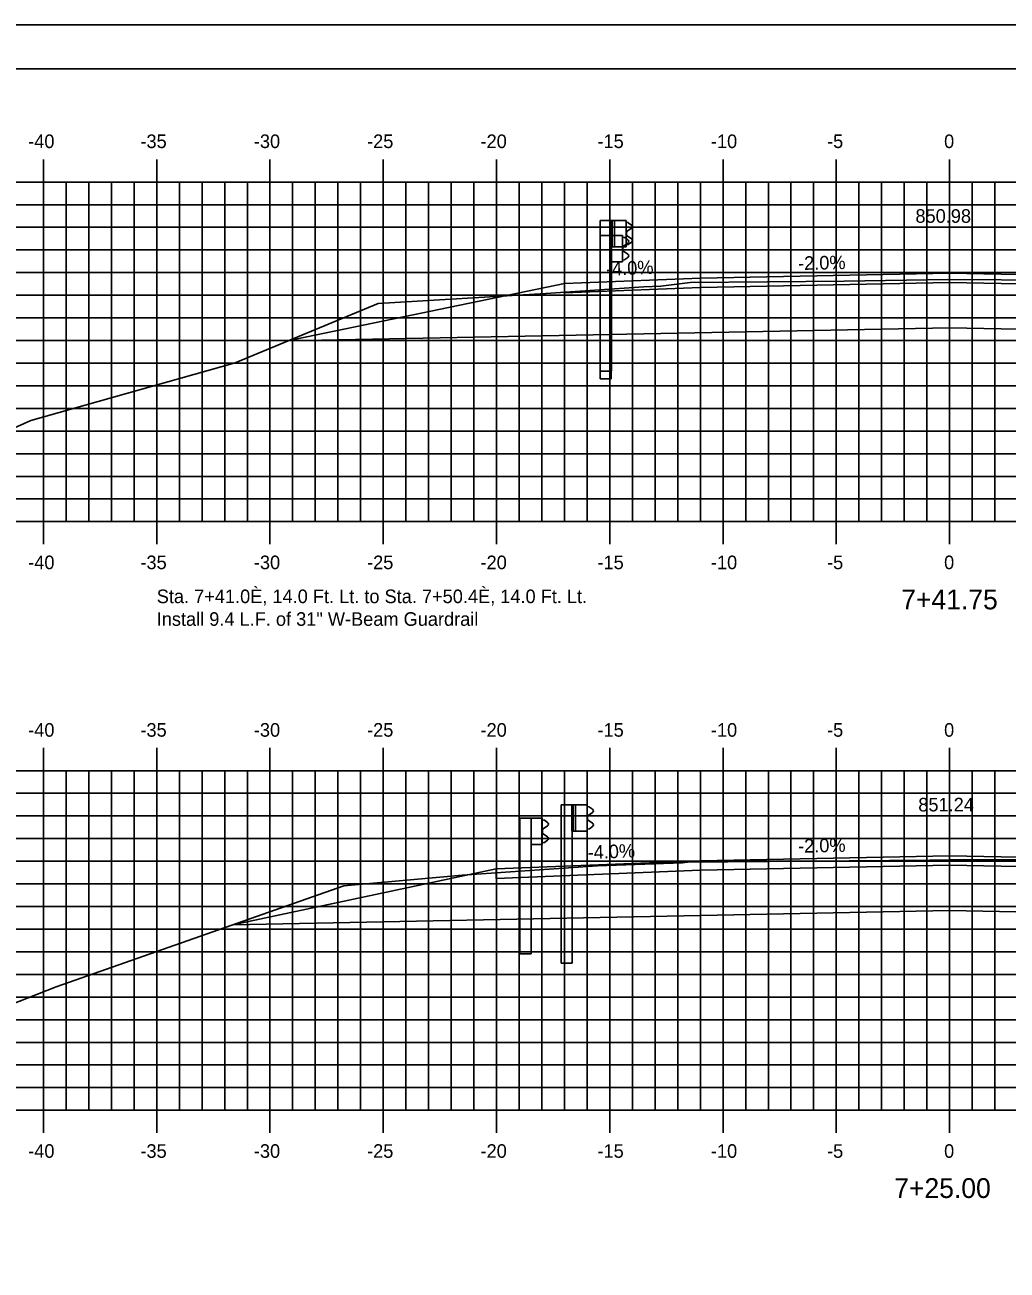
# Model space of a CAD drawing. Extents: x 2194004 to 2194525, y 863888 to 863998.
# Drawn here: x 2194214.2 to 2194257.5, y 863943.4 to 863998.4 of the extents above; entities that cross this region are included whole.
import ezdxf

# ---------------------------------------------------------------- set-up
doc = ezdxf.new("R2010")
doc.units = 0
for name, color, linetype in [('ANNOTATION', 7, 'Continuous'), ('BORDER', 7, 'Continuous'), ('D_Guardrail_Beam_Lt', 7, 'Continuous'), ('H_V ANNOTATION', 7, 'Continuous'), ('MAJOR', 7, 'Continuous'), ('MINOR', 7, 'Continuous'), ('PLOT BOUNDARY', 7, 'Continuous'), ('S_Guardrail_Beam', 7, 'Continuous'), ('S_Roadway_Centerline', 7, 'Continuous'), ('TEMPLATE', 7, 'Continuous')]:
    doc.layers.add(name, color=color, linetype=linetype)

msp = doc.modelspace()

# ---------------------------------------------------------------- linework, layer by layer
at = {"layer": 'BORDER'}
msp.add_lwpolyline([(2194179.986, 863891.446), (2194339.986, 863891.446), (2194339.986, 863996.446), (2194179.986, 863996.446)], close=True, dxfattribs=at)
at = {"layer": 'D_Guardrail_Beam_Lt'}
for p, q in [((2194239.557, 863989.752), (2194239.557, 863982.752)), ((2194240.028, 863989.752), (2194239.557, 863989.752)), ((2194240.715, 863989.752), (2194240.028, 863989.752)), ((2194240.028, 863989.752), (2194240.028, 863988.586)), ((2194240.09, 863989.752), (2194240.09, 863988.586)), ((2194240.195, 863989.752), (2194240.195, 863988.586)), ((2194240.715, 863988.586), (2194240.715, 863989.752)), ((2194240.715, 863989.669), (2194240.79, 863989.655)), ((2194240.805, 863989.648), (2194240.949, 863989.548)), ((2194240.72, 863989.204), (2194240.72, 863989.134)), ((2194240.949, 863989.405), (2194240.753, 863989.269)), ((2194240.753, 863989.07), (2194240.949, 863988.933)), ((2194240.028, 863988.586), (2194240.715, 863988.586)), ((2194240.049, 863982.752), (2194240.049, 863988.586)), ((2194240.79, 863988.684), (2194240.715, 863988.669)), ((2194240.949, 863988.79), (2194240.805, 863988.69)), ((2194240.049, 863982.752), (2194239.557, 863982.752)), ((2194237.836, 863963.944), (2194237.836, 863956.944)), ((2194238.307, 863963.944), (2194237.836, 863963.944)), ((2194238.994, 863963.944), (2194238.307, 863963.944)), ((2194238.307, 863963.944), (2194238.307, 863962.777)), ((2194238.369, 863963.944), (2194238.369, 863962.777)), ((2194238.474, 863963.944), (2194238.474, 863962.777)), ((2194238.994, 863962.777), (2194238.994, 863963.944)), ((2194238.994, 863963.86), (2194239.069, 863963.846)), ((2194239.084, 863963.839), (2194239.228, 863963.739)), ((2194238.999, 863963.395), (2194238.999, 863963.325)), ((2194239.228, 863963.596), (2194239.032, 863963.46)), ((2194239.032, 863963.261), (2194239.228, 863963.125)), ((2194238.307, 863962.777), (2194238.994, 863962.777)), ((2194238.328, 863956.944), (2194238.328, 863962.777)), ((2194239.069, 863962.875), (2194238.994, 863962.86)), ((2194239.228, 863962.982), (2194239.084, 863962.882)), ((2194238.328, 863956.944), (2194237.836, 863956.944))]:
    msp.add_line(p, q, dxfattribs=at)
for centre, major_axis, start_param, end_param in [((2194240.781, 863989.614), (0.0417, 0), 0.959931, 1.376053), ((2194240.898, 863989.476), (0.0877, 0), 5.323254, 7.243116), ((2194240.799, 863989.204), (-0.0789, 0), 5.323254, 6.283185), ((2194240.799, 863989.134), (-0.0789, 0), 6.283185, 7.243116), ((2194240.781, 863988.724), (0.0417, 0), 4.907132, 5.323254), ((2194240.898, 863988.862), (0.0877, 0), 5.323254, 7.243116), ((2194239.06, 863963.805), (0.0417, 0), 0.959931, 1.376053), ((2194239.177, 863963.667), (0.0877, 0), 5.323254, 7.243116), ((2194239.078, 863963.395), (-0.0789, 0), 5.323254, 6.283185), ((2194239.078, 863963.325), (-0.0789, 0), 6.283185, 7.243116), ((2194239.177, 863963.053), (0.0877, 0), 5.323254, 7.243116), ((2194239.06, 863962.916), (0.0417, 0), 4.907132, 5.323254)]:
    msp.add_ellipse(centre, major_axis=major_axis, ratio=0.995501, start_param=start_param, end_param=end_param, dxfattribs=at)
at = {"layer": 'MAJOR'}
for p, q in [((2194214.986, 863992.448), (2194214.986, 863991.446)), ((2194219.986, 863992.448), (2194219.986, 863991.446)), ((2194224.986, 863992.448), (2194224.986, 863991.446)), ((2194229.986, 863992.448), (2194229.986, 863991.446)), ((2194234.986, 863992.448), (2194234.986, 863991.446)), ((2194239.986, 863992.448), (2194239.986, 863991.446)), ((2194244.986, 863992.448), (2194244.986, 863991.446)), ((2194249.986, 863992.448), (2194249.986, 863991.446)), ((2194254.986, 863992.448), (2194254.986, 863991.446)), ((2194184.986, 863991.446), (2194324.986, 863991.446)), ((2194214.986, 863976.446), (2194214.986, 863991.446)), ((2194219.986, 863976.446), (2194219.986, 863991.446)), ((2194224.986, 863976.446), (2194224.986, 863991.446)), ((2194229.986, 863976.446), (2194229.986, 863991.446)), ((2194234.986, 863976.446), (2194234.986, 863991.446)), ((2194239.986, 863976.446), (2194239.986, 863991.446)), ((2194244.986, 863976.446), (2194244.986, 863991.446)), ((2194249.986, 863976.446), (2194249.986, 863991.446)), ((2194254.986, 863976.446), (2194254.986, 863991.446)), ((2194184.986, 863986.446), (2194324.986, 863986.446)), ((2194184.986, 863981.446), (2194324.986, 863981.446)), ((2194184.986, 863976.446), (2194324.986, 863976.446)), ((2194214.986, 863975.444), (2194214.986, 863976.446)), ((2194219.986, 863975.444), (2194219.986, 863976.446)), ((2194224.986, 863975.444), (2194224.986, 863976.446)), ((2194229.986, 863975.444), (2194229.986, 863976.446)), ((2194234.986, 863975.444), (2194234.986, 863976.446)), ((2194239.986, 863975.444), (2194239.986, 863976.446)), ((2194244.986, 863975.444), (2194244.986, 863976.446)), ((2194249.986, 863975.444), (2194249.986, 863976.446)), ((2194254.986, 863975.444), (2194254.986, 863976.446)), ((2194214.986, 863966.448), (2194214.986, 863965.446)), ((2194219.986, 863966.448), (2194219.986, 863965.446)), ((2194224.986, 863966.448), (2194224.986, 863965.446)), ((2194229.986, 863966.448), (2194229.986, 863965.446)), ((2194234.986, 863966.448), (2194234.986, 863965.446)), ((2194239.986, 863966.448), (2194239.986, 863965.446)), ((2194244.986, 863966.448), (2194244.986, 863965.446)), ((2194249.986, 863966.448), (2194249.986, 863965.446)), ((2194254.986, 863966.448), (2194254.986, 863965.446)), ((2194184.986, 863965.446), (2194324.986, 863965.446)), ((2194214.986, 863950.446), (2194214.986, 863965.446)), ((2194219.986, 863950.446), (2194219.986, 863965.446)), ((2194224.986, 863950.446), (2194224.986, 863965.446)), ((2194229.986, 863950.446), (2194229.986, 863965.446)), ((2194234.986, 863950.446), (2194234.986, 863965.446)), ((2194239.986, 863950.446), (2194239.986, 863965.446)), ((2194244.986, 863950.446), (2194244.986, 863965.446)), ((2194249.986, 863950.446), (2194249.986, 863965.446)), ((2194254.986, 863950.446), (2194254.986, 863965.446)), ((2194184.986, 863960.446), (2194324.986, 863960.446)), ((2194184.986, 863955.446), (2194324.986, 863955.446)), ((2194184.986, 863950.446), (2194324.986, 863950.446)), ((2194214.986, 863949.444), (2194214.986, 863950.446)), ((2194219.986, 863949.444), (2194219.986, 863950.446)), ((2194224.986, 863949.444), (2194224.986, 863950.446)), ((2194229.986, 863949.444), (2194229.986, 863950.446)), ((2194234.986, 863949.444), (2194234.986, 863950.446)), ((2194239.986, 863949.444), (2194239.986, 863950.446)), ((2194244.986, 863949.444), (2194244.986, 863950.446)), ((2194249.986, 863949.444), (2194249.986, 863950.446)), ((2194254.986, 863949.444), (2194254.986, 863950.446))]:
    msp.add_line(p, q, dxfattribs=at)
at = {"layer": 'MINOR'}
for p, q in [((2194215.986, 863976.446), (2194215.986, 863991.446)), ((2194216.986, 863976.446), (2194216.986, 863991.446)), ((2194217.986, 863976.446), (2194217.986, 863991.446)), ((2194218.986, 863976.446), (2194218.986, 863991.446)), ((2194220.986, 863976.446), (2194220.986, 863991.446)), ((2194221.986, 863976.446), (2194221.986, 863991.446)), ((2194222.986, 863976.446), (2194222.986, 863991.446)), ((2194223.986, 863976.446), (2194223.986, 863991.446)), ((2194225.986, 863976.446), (2194225.986, 863991.446)), ((2194226.986, 863976.446), (2194226.986, 863991.446)), ((2194227.986, 863976.446), (2194227.986, 863991.446)), ((2194228.986, 863976.446), (2194228.986, 863991.446)), ((2194230.986, 863976.446), (2194230.986, 863991.446)), ((2194231.986, 863976.446), (2194231.986, 863991.446)), ((2194232.986, 863976.446), (2194232.986, 863991.446)), ((2194233.986, 863976.446), (2194233.986, 863991.446)), ((2194235.986, 863976.446), (2194235.986, 863991.446)), ((2194236.986, 863976.446), (2194236.986, 863991.446)), ((2194237.986, 863976.446), (2194237.986, 863991.446)), ((2194238.986, 863976.446), (2194238.986, 863991.446)), ((2194240.986, 863976.446), (2194240.986, 863991.446)), ((2194241.986, 863976.446), (2194241.986, 863991.446)), ((2194242.986, 863976.446), (2194242.986, 863991.446)), ((2194243.986, 863976.446), (2194243.986, 863991.446)), ((2194245.986, 863976.446), (2194245.986, 863991.446)), ((2194246.986, 863976.446), (2194246.986, 863991.446)), ((2194247.986, 863976.446), (2194247.986, 863991.446)), ((2194248.986, 863976.446), (2194248.986, 863991.446)), ((2194250.986, 863976.446), (2194250.986, 863991.446)), ((2194251.986, 863976.446), (2194251.986, 863991.446)), ((2194252.986, 863976.446), (2194252.986, 863991.446)), ((2194253.986, 863976.446), (2194253.986, 863991.446)), ((2194255.986, 863976.446), (2194255.986, 863991.446)), ((2194256.986, 863976.446), (2194256.986, 863991.446)), ((2194184.986, 863990.446), (2194324.986, 863990.446)), ((2194184.986, 863989.446), (2194324.986, 863989.446)), ((2194184.986, 863988.446), (2194324.986, 863988.446)), ((2194184.986, 863987.446), (2194324.986, 863987.446)), ((2194184.986, 863985.446), (2194324.986, 863985.446)), ((2194184.986, 863984.446), (2194324.986, 863984.446)), ((2194184.986, 863983.446), (2194324.986, 863983.446)), ((2194184.986, 863982.446), (2194324.986, 863982.446)), ((2194184.986, 863980.446), (2194324.986, 863980.446)), ((2194184.986, 863979.446), (2194324.986, 863979.446)), ((2194184.986, 863978.446), (2194324.986, 863978.446)), ((2194184.986, 863977.446), (2194324.986, 863977.446)), ((2194215.986, 863950.446), (2194215.986, 863965.446)), ((2194216.986, 863950.446), (2194216.986, 863965.446)), ((2194217.986, 863950.446), (2194217.986, 863965.446)), ((2194218.986, 863950.446), (2194218.986, 863965.446)), ((2194220.986, 863950.446), (2194220.986, 863965.446)), ((2194221.986, 863950.446), (2194221.986, 863965.446)), ((2194222.986, 863950.446), (2194222.986, 863965.446)), ((2194223.986, 863950.446), (2194223.986, 863965.446)), ((2194225.986, 863950.446), (2194225.986, 863965.446)), ((2194226.986, 863950.446), (2194226.986, 863965.446)), ((2194227.986, 863950.446), (2194227.986, 863965.446)), ((2194228.986, 863950.446), (2194228.986, 863965.446)), ((2194230.986, 863950.446), (2194230.986, 863965.446)), ((2194231.986, 863950.446), (2194231.986, 863965.446)), ((2194232.986, 863950.446), (2194232.986, 863965.446)), ((2194233.986, 863950.446), (2194233.986, 863965.446)), ((2194235.986, 863950.446), (2194235.986, 863965.446)), ((2194236.986, 863950.446), (2194236.986, 863965.446)), ((2194237.986, 863950.446), (2194237.986, 863965.446)), ((2194238.986, 863950.446), (2194238.986, 863965.446)), ((2194240.986, 863950.446), (2194240.986, 863965.446)), ((2194241.986, 863950.446), (2194241.986, 863965.446)), ((2194242.986, 863950.446), (2194242.986, 863965.446)), ((2194243.986, 863950.446), (2194243.986, 863965.446)), ((2194245.986, 863950.446), (2194245.986, 863965.446)), ((2194246.986, 863950.446), (2194246.986, 863965.446)), ((2194247.986, 863950.446), (2194247.986, 863965.446)), ((2194248.986, 863950.446), (2194248.986, 863965.446)), ((2194250.986, 863950.446), (2194250.986, 863965.446)), ((2194251.986, 863950.446), (2194251.986, 863965.446)), ((2194252.986, 863950.446), (2194252.986, 863965.446)), ((2194253.986, 863950.446), (2194253.986, 863965.446)), ((2194255.986, 863950.446), (2194255.986, 863965.446)), ((2194256.986, 863950.446), (2194256.986, 863965.446)), ((2194184.986, 863964.446), (2194324.986, 863964.446)), ((2194184.986, 863963.446), (2194324.986, 863963.446)), ((2194184.986, 863962.446), (2194324.986, 863962.446)), ((2194184.986, 863961.446), (2194324.986, 863961.446)), ((2194184.986, 863959.446), (2194324.986, 863959.446)), ((2194184.986, 863958.446), (2194324.986, 863958.446)), ((2194184.986, 863957.446), (2194324.986, 863957.446)), ((2194184.986, 863956.446), (2194324.986, 863956.446)), ((2194184.986, 863954.446), (2194324.986, 863954.446)), ((2194184.986, 863953.446), (2194324.986, 863953.446)), ((2194184.986, 863952.446), (2194324.986, 863952.446)), ((2194184.986, 863951.446), (2194324.986, 863951.446))]:
    msp.add_line(p, q, dxfattribs=at)
at = {"layer": 'PLOT BOUNDARY'}
msp.add_lwpolyline([(2194171.893, 863888.387), (2194341.893, 863888.387), (2194341.893, 863998.387), (2194171.893, 863998.387)], close=True, dxfattribs=at)
at = {"layer": 'S_Guardrail_Beam'}
for p, q in [((2194239.565, 863989.091), (2194239.565, 863983.091)), ((2194240.057, 863989.091), (2194239.565, 863989.091)), ((2194240.546, 863989.091), (2194240.057, 863989.091)), ((2194240.057, 863989.091), (2194240.057, 863987.924)), ((2194240.546, 863987.924), (2194240.546, 863989.091)), ((2194240.546, 863989.018), (2194240.628, 863989.003)), ((2194240.645, 863988.996), (2194240.788, 863988.896)), ((2194240.559, 863988.553), (2194240.559, 863988.462)), ((2194240.788, 863988.753), (2194240.593, 863988.617)), ((2194240.057, 863983.091), (2194240.057, 863987.924)), ((2194240.057, 863987.924), (2194240.546, 863987.924)), ((2194240.628, 863988.011), (2194240.546, 863987.997)), ((2194240.593, 863988.397), (2194240.788, 863988.261)), ((2194240.788, 863988.118), (2194240.645, 863988.018)), ((2194240.057, 863983.091), (2194239.565, 863983.091)), ((2194236.018, 863963.352), (2194236.018, 863957.352)), ((2194236.51, 863963.352), (2194236.018, 863963.352)), ((2194236.999, 863963.352), (2194236.51, 863963.352)), ((2194236.51, 863963.352), (2194236.51, 863962.185)), ((2194236.999, 863962.185), (2194236.999, 863963.352)), ((2194236.999, 863963.279), (2194237.081, 863963.264)), ((2194237.098, 863963.257), (2194237.241, 863963.157)), ((2194237.012, 863962.814), (2194237.012, 863962.723)), ((2194237.241, 863963.014), (2194237.046, 863962.878)), ((2194237.046, 863962.658), (2194237.241, 863962.522)), ((2194236.51, 863957.352), (2194236.51, 863962.185)), ((2194236.51, 863962.185), (2194236.999, 863962.185)), ((2194237.081, 863962.272), (2194236.999, 863962.258)), ((2194237.241, 863962.379), (2194237.098, 863962.279)), ((2194236.51, 863957.352), (2194236.018, 863957.352))]:
    msp.add_line(p, q, dxfattribs=at)
for centre, major_axis, start_param, end_param in [((2194240.621, 863988.962), (0.0417, 0), 0.959931, 1.396263), ((2194240.638, 863988.553), (-0.0789, 0), 5.323254, 6.283185), ((2194240.638, 863988.462), (-0.0789, 0), 6.283185, 7.243116), ((2194240.738, 863988.825), (0.0877, 0), 5.323254, 7.243116), ((2194240.621, 863988.052), (0.0417, 0), 4.886922, 5.323254), ((2194240.738, 863988.19), (0.0877, 0), 5.323254, 7.243116), ((2194237.074, 863963.223), (0.0417, 0), 0.959931, 1.396263), ((2194237.191, 863963.086), (0.0877, 0), 5.323254, 7.243116), ((2194237.091, 863962.814), (-0.0789, 0), 5.323254, 6.283185), ((2194237.091, 863962.723), (-0.0789, 0), 6.283185, 7.243116), ((2194237.074, 863962.313), (0.0417, 0), 4.886922, 5.323254), ((2194237.191, 863962.451), (0.0877, 0), 5.323254, 7.243116)]:
    msp.add_ellipse(centre, major_axis=major_axis, ratio=0.995501, start_param=start_param, end_param=end_param, dxfattribs=at)
at = {"layer": 'S_Roadway_Centerline'}
for points in [[(2194213.418, 863980.464), (2194214.429, 863980.92), (2194223.452, 863983.465), (2194229.766, 863986.085), (2194237.17, 863986.524), (2194241.493, 863986.815), (2194242.245, 863986.842), (2194243.54, 863987.01), (2194250.337, 863987.069), (2194254.913, 863987.141), (2194259.636, 863987.117), (2194266.23, 863987.133), (2194268.49, 863987.008), (2194272.502, 863986.802), (2194276.144, 863985.803), (2194280.132, 863984.18), (2194281.922, 863983.566), (2194282.269, 863983.567), (2194286.889, 863983.115)], [(2194184.986, 863954.358), (2194200.571, 863955.358), (2194201.834, 863955.126), (2194206.87, 863954.31), (2194208.212, 863954.697), (2194211.397, 863954.921), (2194213.079, 863954.925), (2194215.549, 863955.904), (2194228.253, 863960.358), (2194233.476, 863960.836), (2194239.439, 863961.237), (2194243.192, 863961.374), (2194243.421, 863961.404), (2194254.114, 863961.496), (2194254.957, 863961.51), (2194255.828, 863961.505), (2194266.219, 863961.53), (2194266.624, 863961.508), (2194272.966, 863961.182), (2194273.834, 863960.944), (2194274.785, 863960.557), (2194281.743, 863958.166), (2194283.095, 863958.173)]]:
    msp.add_lwpolyline(points, dxfattribs=at)
at = {"layer": 'TEMPLATE'}
for p, q in [((2194243.986, 863987.206), (2194254.986, 863987.426)), ((2194254.986, 863987.426), (2194243.986, 863987.206)), ((2194265.986, 863987.206), (2194254.986, 863987.426)), ((2194237.986, 863986.966), (2194225.765, 863984.425)), ((2194237.986, 863986.966), (2194243.986, 863987.206)), ((2194243.986, 863987.206), (2194237.986, 863986.966)), ((2194237.986, 863986.966), (2194237.986, 863986.966)), ((2194254.986, 863987.009), (2194243.986, 863986.789)), ((2194265.986, 863986.789), (2194254.986, 863987.009)), ((2194254.986, 863985.009), (2194225.765, 863984.425)), ((2194279.291, 863984.523), (2194254.986, 863985.009)), ((2194243.986, 863961.466), (2194234.974, 863961.105)), ((2194243.986, 863961.466), (2194254.986, 863961.686)), ((2194254.986, 863961.686), (2194243.986, 863961.466)), ((2194265.986, 863961.466), (2194254.986, 863961.686)), ((2194234.974, 863961.105), (2194223.342, 863958.636)), ((2194243.986, 863961.049), (2194254.986, 863961.269)), ((2194265.986, 863961.049), (2194254.986, 863961.269))]:
    msp.add_line(p, q, dxfattribs=at)
for points in [[(2194243.986, 863986.789), (2194237.986, 863986.549), (2194237.986, 863986.966)], [(2194234.974, 863961.105), (2194234.974, 863960.689), (2194243.986, 863961.049)], [(2194223.342, 863958.636), (2194243.986, 863959.049), (2194254.986, 863959.269), (2194265.986, 863959.049), (2194279.987, 863958.769)]]:
    msp.add_lwpolyline(points, dxfattribs=at)

# ---------------------------------------------------------------- texts
at = {"layer": 'ANNOTATION'}
for s, p in [('850.98', (2194253.48, 863989.646)), ('Sta. 7+41.0È, 14.0 Ft. Lt. to Sta. 7+50.4È, 14.0 Ft. Lt.', (2194219.986, 863972.846)), ('Install 9.4 L.F. of 31" W-Beam Guardrail', (2194219.986, 863971.844)), ('851.24', (2194253.606, 863963.646))]:
    msp.add_text(s, height=0.6, dxfattribs=at).set_placement(p)
for s, rotation, p in [('-4.0%', 2.2906, (2194239.831, 863987.307)), ('-2.0%', 1.1458, (2194248.304, 863987.559)), ('-4.0%', 2.2906, (2194239.019, 863961.534)), ('-2.0%', 1.1458, (2194248.304, 863961.819))]:
    msp.add_text(s, height=0.6, rotation=rotation, dxfattribs=at).set_placement(p)
at = {"layer": 'H_V ANNOTATION'}
for s, height, p in [('-40', 0.6, (2194214.312, 863992.946)), ('-35', 0.6, (2194219.266, 863992.946)), ('-30', 0.6, (2194224.274, 863992.946)), ('-25', 0.6, (2194229.272, 863992.946)), ('-20', 0.6, (2194234.28, 863992.946)), ('-15', 0.6, (2194239.443, 863992.946)), ('-10', 0.6, (2194244.451, 863992.946)), ('-5', 0.6, (2194249.577, 863992.946)), ('0', 0.6, (2194254.745, 863992.946)), ('-40', 0.6, (2194214.312, 863974.346)), ('-35', 0.6, (2194219.266, 863974.346)), ('-30', 0.6, (2194224.274, 863974.346)), ('-25', 0.6, (2194229.272, 863974.346)), ('-20', 0.6, (2194234.28, 863974.346)), ('-15', 0.6, (2194239.443, 863974.346)), ('-10', 0.6, (2194244.451, 863974.346)), ('-5', 0.6, (2194249.577, 863974.346)), ('0', 0.6, (2194254.745, 863974.346)), ('7+41.75', 0.875, (2194252.852, 863972.571)), ('-40', 0.6, (2194214.312, 863966.946)), ('-35', 0.6, (2194219.266, 863966.946)), ('-30', 0.6, (2194224.274, 863966.946)), ('-25', 0.6, (2194229.272, 863966.946)), ('-20', 0.6, (2194234.28, 863966.946)), ('-15', 0.6, (2194239.443, 863966.946)), ('-10', 0.6, (2194244.451, 863966.946)), ('-5', 0.6, (2194249.577, 863966.946)), ('0', 0.6, (2194254.745, 863966.946)), ('-40', 0.6, (2194214.312, 863948.346)), ('-35', 0.6, (2194219.266, 863948.346)), ('-30', 0.6, (2194224.274, 863948.346)), ('-25', 0.6, (2194229.272, 863948.346)), ('-20', 0.6, (2194234.28, 863948.346)), ('-15', 0.6, (2194239.443, 863948.346)), ('-10', 0.6, (2194244.451, 863948.346)), ('-5', 0.6, (2194249.577, 863948.346)), ('0', 0.6, (2194254.745, 863948.346)), ('7+25.00', 0.875, (2194252.544, 863946.571))]:
    msp.add_text(s, height=height, dxfattribs=at).set_placement(p)
at = {"layer": 'TEMPLATE'}
for s, p in [('C', (2194254.908, 863987.141)), ('L', (2194254.913, 863987.134))]:
    msp.add_text(s, height=0.0146, dxfattribs=at).set_placement(p)

doc.saveas('drawing.dxf')
